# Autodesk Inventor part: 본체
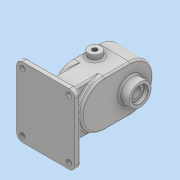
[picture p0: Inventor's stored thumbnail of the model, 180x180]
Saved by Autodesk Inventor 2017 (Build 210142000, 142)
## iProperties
Part Number: 본체
Material: 일반
Document SubType Name: Modeling
Designer: 222
Density: 1 g/cm^3
Appearance: 기본값
Author: 222
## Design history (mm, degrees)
sketch "스케치1"
  geometry: L1 (22, 0)-(-22, 0); L2 (22, -40)-(-22, -40); L3 (-22, 40)-(22, 40); A1 r 40 centre (22, 0) between (22, -40) and (22, 40); A2 r 40 centre (-22, 0) between (-22, 40) and (-22, -40); 2 further points
  constraints: 8 end point, 4 point on circle, 4 tangent, 2 centre point, 1 coincident, 1 horizontal, 1 midpoint, 1 parallel
  dimensions: "d0" = 40 radius of A1; "d1" = 44 distance of L3.start L3.end
extrude "돌출1" new body sketch "스케치1" stored distance "d2" = 53; taper "d3" = 0 deg
sketch "스케치2"
  geometry: L1 (0, -22)-(0, 22); L2 (-24, -22)-(-24, 22); L3 (24, 22)-(24, -22); A1 r 24 centre (0, -22) between (-24, -22) and (24, -22); A2 r 24 centre (0, 22) between (24, 22) and (-24, 22); 2 further points
  constraints: 8 end point, 4 point on circle, 4 tangent, 2 centre point, 1 coincident, 1 midpoint, 1 parallel, 1 vertical
  dimensions: "d4" = 24 radius of A2; "d5" = 44 distance of L3.start L3.end
extrude "돌출2" cut sketch "스케치2" distance "d6" = 29; taper "d7" = 0 deg
sketch "스케치3"
  geometry: C1 r 19 at (0, 22); A1 r 40 centre (0, 22) between (40, 22) and (-40, 22) reference; 1 further point
  constraints: 1 centre point, 1 coincident
  dimensions: "d8" = 38 diameter of C1
extrude "돌출3" join sketch "스케치3" distance "d9" = 17; taper "d10" = 0 deg
hole "구멍1" diameter "d13" = 28; stored, may be unused: countersink angle "d17" = 90 deg, drill point angle "d19" = 0 deg; dims "d14" = 6, "d15" = 4, "d16" = 2, "d18" = 7.3, "d100" = 10, "d101" = 10
hole "구멍2" diameter "d22" = 25; stored, may be unused: countersink angle "d26" = 90 deg, drill point angle "d28" = 0 deg; dims "d20" = 10, "d21" = 10, "d23" = 6, "d24" = 4, "d25" = 2, "d27" = 15
hole "구멍3" diameter "d31" = 17; stored, may be unused: countersink angle "d35" = 90 deg, drill point angle "d37" = 0 deg; dims "d29" = 10, "d30" = 10, "d32" = 6, "d33" = 4, "d34" = 2, "d36" = 15
hole "구멍4" diameter "d40" = 25; stored, may be unused: countersink angle "d44" = 90 deg, drill point angle "d46" = 0 deg; dims "d38" = 10, "d39" = 10, "d41" = 6, "d42" = 4, "d43" = 2, "d45" = 15
sketch "스케치5"
  geometry: L1 (0, 0)-(0, 44) reference; C1 r 11 at (14, 22); 1 further point
  constraints: 1 centre point, 1 horizontal alignment
  dimensions: "d47" = 22 diameter of C1; "d48" = 14 distance from line of C1.centre L1
extrude "돌출4" join sketch "스케치5" distance "d49" = 10; taper "d50" = 0 deg
hole "구멍5" diameter "d53" = 8.376; stored, may be unused: countersink angle "d57" = 90 deg, drill point angle "d59" = 0 deg; dims "d51" = 10, "d52" = 10, "d54" = 20, "d55" = 4, "d56" = 2, "d58" = 27.3
sketch "스케치6"
  geometry: L1 (40, -22)-(40, 22) reference; L2 (-40, 22)-(-40, -22) reference; L3 (31, 22)-(31, -22); L4 (-31, -22)-(-31, 22); A1 r 40 centre (0, 22) between (40, 22) and (-40, 22) reference; A2 r 40 centre (0, -22) between (-40, -22) and (40, -22) reference; A3 r 31 centre (0, 22) between (31, 22) and (-31, 22); A4 r 31 centre (0, -22) between (-31, -22) and (31, -22); 7 further points
  constraints: 6 point on circle, 4 coincident, 4 end point, 2 centre point, 3 other
  dimensions: "d60" = 31 radius of A3
hole "구멍6" sketch "스케치6" at (0, 53), (-31, 22), (31, 22), (31, -22), (-31, -22), (0, -53) diameter "d61" = 4.134; stored, may be unused: countersink angle "d65" = 90 deg, drill point angle "d67" = 118 deg; dims "d62" = 10, "d63" = 4, "d64" = 2, "d66" = 12
node "작업 평면1"
sketch "스케치7"
  geometry: L1 (56.5, -60)-(-43.5, -60); L2 (-43.5, -60)-(-43.5, 60); L3 (-43.5, 60)-(56.5, 60); L4 (56.5, 60)-(56.5, -60); L5 (-43.5, 19)-(-43.5, -19) reference; 2 further points
  constraints: 8 end point, 2 midpoint, 2 parallel, 1 horizontal, 1 perpendicular
  dimensions: "d69" = 100 distance of L1.start L1.end; "d70" = 120 distance of L3.end L1.start
extrude "돌출5" join sketch "스케치7" distance "d71" = 10; taper "d72" = 0 deg
sketch "스케치8"
  geometry: L1 (18.5, 40)-(-18.5, 40); L2 (-18.5, 40)-(-18.5, -40); L3 (-18.5, -40)-(18.5, -40); L4 (18.5, -40)-(18.5, 40); L5 (43.5, 60)-(43.5, -60) reference; L6 (-26.5, 40)-(26.5, 40) reference; L7 (26.5, -40)-(-26.5, -40) reference; 1 further point
  constraints: 8 end point, 2 parallel, 1 collinear, 1 horizontal, 1 perpendicular
  dimensions: "d73" = 80 distance of L3.end L1.start; "d74" = 37 distance of L2.end L3.end; "d75" = 25 distance between parallel lines of L4 L5
extrude "돌출6" join sketch "스케치8" stored distance "d76" = 10; taper "d77" = 0 deg
sketch "스케치9"
  geometry: L1 (43.5, 60)-(-56.5, 60) reference; L2 (-56.5, 60)-(-56.5, -60) reference; 2 further points
  constraints: 1 other
  dimensions: "d78" = 60 distance from line of point (-44.5, 0) L1; "d79" = 12 distance from line of point (-44.5, 0) L2
feature "엠보싱1" sketch "스케치9" dims "d0" = 40, "d1" = 44, "d80" = 0.5, "d81" = 0
fillet "모깎기1" dims "d82" = 10
sketch "스케치10"
  geometry: A1 r 10 centre (-46.5, -50) between (-56.5, -50) and (-46.5, -60) reference; A2 r 10 centre (-46.5, 50) between (-46.5, 60) and (-56.5, 50) reference; A3 r 10 centre (33.5, 50) between (43.5, 50) and (33.5, 60) reference; A4 r 10 centre (33.5, -50) between (33.5, -60) and (43.5, -50) reference; 5 further points
  constraints: 4 coincident
hole "구멍7" sketch "스케치10" at (-46.5, -50), (33.5, -50), (33.5, 50), (-46.5, 50) diameter "d83" = 9; stored, may be unused: countersink angle "d87" = 90 deg, drill point angle "d89" = 0 deg; dims "d84" = 10, "d85" = 4, "d86" = 2, "d88" = 12
fillet "모깎기2" dims "d90" = 3
fillet "모깎기3" dims "d91" = 3
fillet "모깎기4" dims "d92" = 3
fillet "모깎기5" dims "d93" = 0.5
chamfer "모따기1" distance "d94" = 0.7; stored, may be unused: second distance "d95" = 2, angle "d96" = 30 deg
chamfer "모따기2" distance "d97" = 1; stored, may be unused: second distance "d98" = 2, angle "d99" = 30 deg
fillet "모깎기6" dims "d102" = 3
node "솔리드1"
mirror "미러1"
